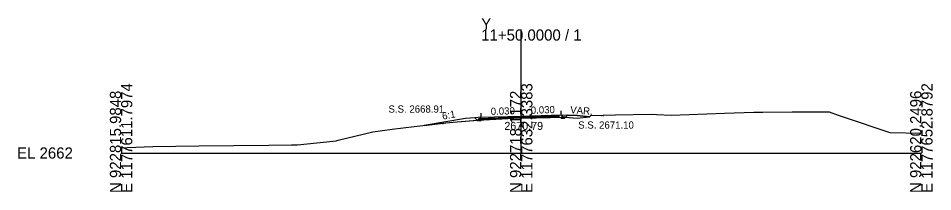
# Model space of a CAD drawing. Extents: x -26 to 203, y -10 to 2034.
# Drawn here: x -25.7 to 202.8, y 1490.3 to 1533.7 of the extents above; entities that cross this region are included whole.
import ezdxf

# ---------------------------------------------------------------- set-up
doc = ezdxf.new("R2010")
doc.units = 0
for name, color, linetype in [('Exist Cross Section Cell', 7, 'Continuous'), ('Exist XS Center Line Elevation Label', 7, 'Continuous'), ('Exist XS Ground Line', 7, 'Continuous'), ('Prop XS Ditch Slope Text', 7, 'Continuous'), ('Prop XS Dump Level', 7, 'Continuous'), ('Prop XS Earthwork Shape', 7, 'Continuous'), ('Prop XS EOT Tick Mark', 7, 'Continuous'), ('Prop XS Finish Grade', 7, 'Continuous'), ('Prop XS Finish Grade Earthwork', 7, 'Continuous'), ('Prop XS Finish Grade Pavement', 7, 'Continuous'), ('Prop XS Pvmt Edge Slope', 7, 'Continuous'), ('Prop XS SE Text', 7, 'Continuous'), ('Prop XS SS Elevation Text', 7, 'Continuous'), ('Prop XS Subgrade Earthwork', 7, 'Continuous'), ('Prop XS Wedging', 7, 'Continuous')]:
    doc.layers.add(name, color=color, linetype=linetype)

msp = doc.modelspace()

# ---------------------------------------------------------------- linework, layer by layer
at = {"layer": 'Exist Cross Section Cell'}
for p, q in [((100, 1500), (100, 1530.94)), ((0, 1500), (100, 1500)), ((100, 1500), (200, 1500))]:
    msp.add_line(p, q, dxfattribs=at)
at = {"layer": 'Exist XS Ground Line'}
for p, q in [((89.15, 1508.26), (96.67, 1508.63)), ((96.67, 1508.63), (99.48, 1508.78)), ((99.48, 1508.78), (100, 1508.79)), ((100, 1508.79), (103.7, 1508.85)), ((103.7, 1508.85), (110.81, 1509)), ((110.81, 1509), (114.02, 1508.7)), ((114.02, 1508.7), (117.05, 1509.09)), ((117.05, 1509.09), (117.39, 1509.43)), ((117.39, 1509.43), (123.6, 1509.55)), ((123.6, 1509.55), (132.48, 1509.72)), ((132.48, 1509.72), (133.77, 1509.62)), ((133.77, 1509.62), (137.57, 1509.44)), ((137.57, 1509.44), (150.8, 1509.95)), ((150.8, 1509.95), (158.11, 1510.25)), ((158.11, 1510.25), (160.35, 1510.26)), ((160.35, 1510.26), (167.69, 1510.29)), ((167.69, 1510.29), (173.32, 1510.31)), ((173.32, 1510.31), (175.05, 1510.29)), ((175.05, 1510.29), (176.95, 1510.27)), ((176.95, 1510.27), (179.24, 1509.46)), ((179.24, 1509.46), (180.5, 1509.03)), ((180.5, 1509.03), (192.13, 1505.11)), ((67.71, 1505.97), (73.24, 1506.61)), ((73.24, 1506.61), (81.17, 1507.56)), ((81.17, 1507.56), (82.96, 1507.71)), ((82.96, 1507.71), (89.15, 1508.26)), ((54.26, 1503.18), (62.93, 1505.29)), ((62.93, 1505.29), (67.71, 1505.97)), ((192.13, 1505.11), (200, 1504.98)), ((1.52, 1501.37), (7.94, 1501.66)), ((7.94, 1501.66), (19.47, 1501.76)), ((19.47, 1501.76), (36.96, 1501.97)), ((36.96, 1501.97), (42.6, 1502.01)), ((42.6, 1502.01), (44.12, 1502.08)), ((44.12, 1502.08), (53.72, 1503.08)), ((53.72, 1503.08), (54.26, 1503.18)), ((0, 1501.33), (1.52, 1501.37))]:
    msp.add_line(p, q, dxfattribs=at)
at = {"layer": 'Prop XS Dump Level'}
for p, q in [((90, 1508.95), (100, 1509.25)), ((100, 1509.25), (110, 1509.55))]:
    msp.add_line(p, q, dxfattribs=at)
at = {"layer": 'Prop XS Earthwork Shape'}
for p, q in [((86.08, 1508.63), (75.73, 1506.91)), ((88.41, 1508.82), (86.08, 1508.63)), ((88.98, 1508.25), (88.41, 1508.82)), ((110.81, 1509), (110, 1508.99)), ((110, 1508.99), (110, 1508.71)), ((110, 1508.71), (110.81, 1508.74)), ((111.05, 1508.98), (110.81, 1509)), ((110.81, 1508.74), (111.05, 1508.98)), ((111.57, 1509.5), (111.05, 1508.98)), ((111.05, 1508.98), (114.02, 1508.7)), ((114, 1509.43), (111.57, 1509.5)), ((117.05, 1509.09), (114, 1509.43)), ((114.02, 1508.7), (117.05, 1509.09)), ((75.73, 1506.91), (81.17, 1507.56)), ((81.17, 1507.56), (82.96, 1507.71)), ((82.96, 1507.71), (88.98, 1508.25)), ((89.15, 1508.26), (88.98, 1508.25)), ((88.98, 1508.25), (89.14, 1508.09)), ((89.14, 1508.09), (90, 1508.11)), ((90, 1508.3), (89.15, 1508.26)), ((90, 1508.11), (90, 1508.3))]:
    msp.add_line(p, q, dxfattribs=at)
at = {"layer": 'Prop XS EOT Tick Mark'}
for p, q in [((90, 1508.95), (90, 1509.95)), ((110, 1509.55), (110, 1510.55))]:
    msp.add_line(p, q, dxfattribs=at)
at = {"layer": 'Prop XS Finish Grade'}
for p, q in [((90, 1508.95), (88.41, 1508.82)), ((110, 1509.55), (111.57, 1509.5))]:
    msp.add_line(p, q, dxfattribs=at)
at = {"layer": 'Prop XS Finish Grade Earthwork'}
for p, q in [((86.08, 1508.63), (75.73, 1506.91)), ((88.41, 1508.82), (86.08, 1508.63)), ((111.57, 1509.5), (114, 1509.43)), ((114, 1509.43), (117.05, 1509.09))]:
    msp.add_line(p, q, dxfattribs=at)
at = {"layer": 'Prop XS Finish Grade Pavement'}
for p, q in [((90, 1508.95), (100, 1509.25)), ((100, 1509.25), (110, 1509.55))]:
    msp.add_line(p, q, dxfattribs=at)
at = {"layer": 'Prop XS Pvmt Edge Slope'}
for p, q in [((90, 1508.95), (89.14, 1508.09)), ((110, 1509.55), (110.81, 1508.74))]:
    msp.add_line(p, q, dxfattribs=at)
at = {"layer": 'Prop XS Subgrade Earthwork'}
for p, q in [((89.14, 1508.09), (88.41, 1508.82)), ((110, 1508.71), (110, 1508.99)), ((110, 1508.71), (110.81, 1508.74)), ((110.81, 1508.74), (111.57, 1509.5)), ((90, 1508.11), (89.14, 1508.09)), ((90, 1508.11), (90, 1508.3))]:
    msp.add_line(p, q, dxfattribs=at)
at = {"layer": 'Prop XS Wedging'}
msp.add_lwpolyline([(89.44, 1508.27), (89.44, 1508.68), (96.67, 1508.9), (99.44, 1508.98), (99.48, 1508.98), (100, 1509), (103.7, 1509.12), (109.44, 1509.32), (109.44, 1508.97), (103.7, 1508.86), (100, 1508.79), (99.48, 1508.78), (99.44, 1508.78), (96.67, 1508.63)], close=True, dxfattribs=at)
msp.add_lwpolyline([(89.44, 1508.27), (89.44, 1508.68), (96.67, 1508.9), (99.44, 1508.98), (99.48, 1508.98), (100, 1509), (103.7, 1509.12), (109.44, 1509.32), (109.44, 1508.97), (103.7, 1508.86), (100, 1508.79), (99.48, 1508.78), (99.44, 1508.78), (96.67, 1508.63)], close=True, dxfattribs=at)
msp.add_lwpolyline([(89.44, 1508.27), (89.44, 1508.68), (96.67, 1508.9), (99.44, 1508.98), (99.48, 1508.98), (100, 1509), (103.7, 1509.12), (109.44, 1509.32), (109.44, 1508.97), (103.7, 1508.86), (100, 1508.79), (99.48, 1508.78), (99.44, 1508.78), (96.67, 1508.63)], close=True, dxfattribs=at)
msp.add_lwpolyline([(89.44, 1508.27), (89.44, 1508.68), (96.67, 1508.9), (99.44, 1508.98), (99.48, 1508.98), (100, 1509), (103.7, 1509.12), (109.44, 1509.32), (109.44, 1508.97), (103.7, 1508.86), (100, 1508.79), (99.48, 1508.78), (99.44, 1508.78), (96.67, 1508.63)], close=True, dxfattribs=at)
msp.add_lwpolyline([(89.44, 1508.27), (89.44, 1508.68), (96.67, 1508.9), (99.44, 1508.98), (99.48, 1508.98), (100, 1509), (103.7, 1509.12), (109.44, 1509.32), (109.44, 1508.97), (103.7, 1508.86), (100, 1508.79), (99.48, 1508.78), (99.44, 1508.78), (96.67, 1508.63)], close=True, dxfattribs=at)
msp.add_lwpolyline([(89.44, 1508.27), (89.44, 1508.68), (96.67, 1508.9), (99.44, 1508.98), (99.48, 1508.98), (100, 1509), (103.7, 1509.12), (109.44, 1509.32), (109.44, 1508.97), (103.7, 1508.86), (100, 1508.79), (99.48, 1508.78), (99.44, 1508.78), (96.67, 1508.63)], close=True, dxfattribs=at)
msp.add_lwpolyline([(89.44, 1508.27), (89.44, 1508.68), (96.67, 1508.9), (99.44, 1508.98), (99.48, 1508.98), (100, 1509), (103.7, 1509.12), (109.44, 1509.32), (109.44, 1508.97), (103.7, 1508.86), (100, 1508.79), (99.48, 1508.78), (99.44, 1508.78), (96.67, 1508.63)], close=True, dxfattribs=at)
msp.add_lwpolyline([(89.44, 1508.27), (89.44, 1508.68), (96.67, 1508.9), (99.44, 1508.98), (99.48, 1508.98), (100, 1509), (103.7, 1509.12), (109.44, 1509.32), (109.44, 1508.97), (103.7, 1508.86), (100, 1508.79), (99.48, 1508.78), (99.44, 1508.78), (96.67, 1508.63)], close=True, dxfattribs=at)

# ---------------------------------------------------------------- texts
at = {"layer": 'Exist Cross Section Cell'}
for s, p in [('Y', (90, 1530.94)), ('11+50.0000 / 1', (90, 1528.14)), ('EL 2662', (-26, 1498.6))]:
    msp.add_text(s, height=2.8, dxfattribs=at).set_placement(p)
for s, p in [('N 922815.9848', (0, 1490)), ('E 1177611.7974', (2.8, 1490)), ('N 922718.1172', (100, 1490)), ('E 1177632.3383', (102.8, 1490)), ('N 922620.2496', (200, 1490)), ('E 1177652.8792', (202.8, 1490))]:
    msp.add_text(s, height=2.8, rotation=90, dxfattribs=at).set_placement(p)
at = {"layer": 'Exist XS Center Line Elevation Label'}
msp.add_text('2670.79', height=2, dxfattribs=at).set_placement((95.79, 1505.79))
at = {"layer": 'Prop XS Ditch Slope Text'}
for s, rotation, p in [('6:1', 10.3172, (80.39, 1508.33)), ('VAR.', 355.4557, (112.2, 1509.96))]:
    msp.add_text(s, height=1.8, rotation=rotation, dxfattribs=at).set_placement(p)
at = {"layer": 'Prop XS Dump Level'}
for s, height, p in [('Case1', 0.04, (86, 1508.59)), ('Case1', 0.04, (114, 1509.39)), ('Eop', 0.3, (120, 1509.2)), ('Eop', 0.3, (80, 1507.09))]:
    msp.add_text(s, height=height, dxfattribs=at).set_placement(p)
at = {"layer": 'Prop XS SE Text'}
for p in [(92.41, 1509.52), (102.41, 1509.82)]:
    msp.add_text('0.030', height=1.8, rotation=1.7184, dxfattribs=at).set_placement(p)
at = {"layer": 'Prop XS SS Elevation Text'}
for s, p in [('S.S. 2668.91', (66.83, 1510.11)), ('S.S. 2671.10', (114.24, 1506.11))]:
    msp.add_text(s, height=1.8, dxfattribs=at).set_placement(p)

doc.saveas('drawing.dxf')
